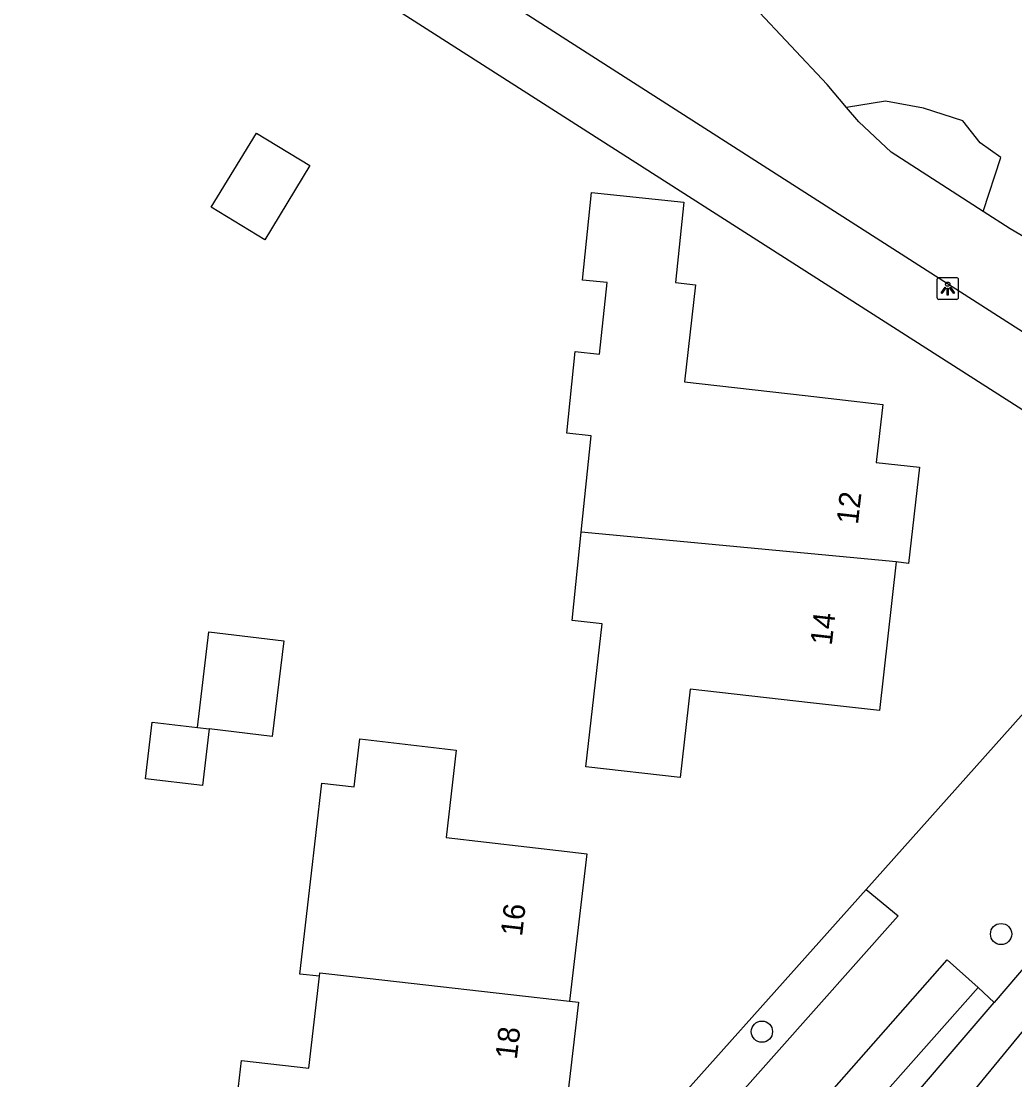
# Model space of a CAD drawing. Extents: x 162398 to 163643, y 386453 to 387397.
# Drawn here: x 162930.19 to 162976.02, y 386684.22 to 386733.04 of the extents above; entities that cross this region are included whole.
import ezdxf

# ---------------------------------------------------------------- set-up
doc = ezdxf.new("R2010")
doc.units = 0
for name, color, linetype in [('IMGEO_Boom', 7, 'Continuous'), ('IMGEO_Groenvoorziening', 7, 'Continuous'), ('IMGEO_Lichtpunt', 7, 'Continuous'), ('IMGEO_Pand', 7, 'Continuous'), ('IMGEO_Pand_nummerreeks', 7, 'Continuous'), ('IMGEO_Rijbaan_lokaal_gesloten', 7, 'Continuous'), ('IMGEO_Voetpad_open', 7, 'Continuous')]:
    doc.layers.add(name, color=color, linetype=linetype)

msp = doc.modelspace()

# ---------------------------------------------------------------- linework, layer by layer
at = {"layer": 'IMGEO_Boom'}
for centre in [(162975.387, 386690.945), (162964.357, 386686.446)]:
    msp.add_circle(centre, 0.489, dxfattribs=at)
at = {"layer": 'IMGEO_Groenvoorziening'}
for points in [[(162968.263, 386729.057), (162967.364, 386730.111), (162964.012, 386733.678)], [(162974.555, 386724.265), (162975.371, 386726.745), (162974.416, 386727.436), (162973.62, 386728.445), (162971.815, 386729.029), (162970.063, 386729.348), (162968.263, 386729.057)], [(162974.555, 386724.265), (162970.324, 386726.991), (162968.831, 386728.392), (162968.263, 386729.057)], [(162989.383, 386718.664), (162983.806, 386718.926), (162982.995, 386719.246), (162975.81, 386723.457), (162974.555, 386724.265)], [(162957.707, 386680.182), (162969.169, 386692.999)]]:
    msp.add_lwpolyline(points, dxfattribs=at)
at = {"layer": 'IMGEO_Lichtpunt'}
for p, q in [((162972.43, 386721.114), (162972.43, 386720.307)), ((162972.43, 386721.114), (162972.43, 386720.307)), ((162973.332, 386721.209), (162972.524, 386721.209)), ((162973.332, 386721.209), (162972.524, 386721.209)), ((162973.426, 386720.307), (162973.426, 386721.114)), ((162973.426, 386720.307), (162973.426, 386721.114)), ((162972.524, 386720.213), (162973.332, 386720.213)), ((162972.524, 386720.213), (162973.332, 386720.213))]:
    msp.add_line(p, q, dxfattribs=at)
for points in [[(162972.804, 386720.778), (162972.843, 386720.75), (162972.655, 386720.488), (162972.617, 386720.515), (162972.804, 386720.778)], [(162972.906, 386720.73), (162972.953, 386720.73), (162972.953, 386720.408), (162972.906, 386720.408), (162972.906, 386720.73)], [(162973.016, 386720.75), (162973.054, 386720.777), (162973.241, 386720.515), (162973.202, 386720.487), (162973.016, 386720.75)]]:
    msp.add_lwpolyline(points, dxfattribs=at)
msp.add_circle((162972.929, 386720.912), 0.0994, dxfattribs=at)
for centre, start, end in [((162972.524, 386721.114), 90, 180), ((162972.524, 386721.114), 90, 180), ((162973.332, 386721.114), 0, 90), ((162973.332, 386721.114), 0, 90), ((162972.524, 386720.307), 180, 270), ((162972.524, 386720.307), 180, 270), ((162973.332, 386720.307), 270, 0), ((162973.332, 386720.307), 270, 360)]:
    msp.add_arc(centre, 0.0946, start, end, dxfattribs=at)
at = {"layer": 'IMGEO_Pand'}
for points in [[(162938.962, 386724.457), (162941.047, 386727.882), (162943.508, 386726.384), (162941.423, 386722.959), (162938.962, 386724.457)], [(162956.024, 386709.48), (162956.483, 386713.921), (162955.357, 386714.037), (162955.747, 386717.808), (162956.872, 386717.691), (162957.212, 386720.986), (162956.086, 386721.102), (162956.503, 386725.141), (162960.758, 386724.7), (162960.374, 386720.991), (162961.298, 386720.886), (162960.789, 386716.404), (162966.35, 386715.773), (162969.927, 386715.367), (162969.624, 386712.693), (162971.622, 386712.466), (162971.12, 386708.039), (162970.552, 386708.103)], [(162970.552, 386708.103), (162969.775, 386701.249), (162966.596, 386701.61), (162961.048, 386702.239), (162960.586, 386698.168), (162956.239, 386698.661), (162956.986, 386705.244), (162955.602, 386705.401), (162956.024, 386709.48)], [(162970.552, 386708.103), (162956.024, 386709.48)], [(162938.32, 386700.477), (162938.85, 386704.888), (162942.305, 386704.472), (162941.774, 386700.054), (162938.857, 386700.411)], [(162938.857, 386700.411), (162938.553, 386697.793), (162935.929, 386698.098), (162936.233, 386700.719), (162938.32, 386700.477)], [(162938.32, 386700.477), (162938.857, 386700.411)], [(162943.946, 386689.002), (162943.045, 386689.101), (162943.538, 386693.351), (162944.066, 386697.904), (162945.549, 386697.732), (162945.806, 386699.946), (162950.259, 386699.43), (162949.792, 386695.4), (162955.382, 386694.753), (162956.276, 386694.649), (162955.488, 386687.856)], [(162955.488, 386687.856), (162955.897, 386687.809), (162955.378, 386683.332), (162953.512, 386683.549), (162953.2, 386680.862), (162949.972, 386681.236), (162944.341, 386681.888), (162943.87, 386677.818), (162939.566, 386678.317), (162940.354, 386685.115), (162943.453, 386684.755), (162943.946, 386689.002)], [(162943.946, 386689.002), (162943.964, 386689.161), (162945.467, 386688.986), (162955.488, 386687.856)]]:
    msp.add_lwpolyline(points, dxfattribs=at)
at = {"layer": 'IMGEO_Rijbaan_lokaal_gesloten'}
msp.add_lwpolyline([(162944.202, 386650.062), (162971.032, 386679.935), (162978.045, 386688.478), (162987.962, 386701.42), (162988.45, 386702.342)], dxfattribs=at)
at = {"layer": 'IMGEO_Voetpad_open'}
for points in [[(162986.397, 386712.298), (162986.082, 386712.5), (162952.63, 386733.915), (162927.211, 386750), (162923.157, 386752.565), (162923.129, 386752.583), (162922.957, 386752.706), (162922.868, 386752.783)], [(162984.352, 386710.007), (162921.76, 386750), (162921.361, 386750.255)], [(162969.169, 386692.999), (162984.352, 386710.007)], [(162969.169, 386692.999), (162970.648, 386691.781), (162959.175, 386678.871)], [(162963.515, 386679.089), (162972.906, 386689.751), (162974.326, 386688.48)], [(162976.679, 386689.682), (162975.063, 386687.793)], [(162974.326, 386688.48), (162964.913, 386677.848)], [(162975.063, 386687.793), (162974.326, 386688.48)], [(162965.843, 386677.132), (162969.738, 386681.565), (162975.063, 386687.793)]]:
    msp.add_lwpolyline(points, dxfattribs=at)

# ---------------------------------------------------------------- texts
at = {"layer": 'IMGEO_Pand_nummerreeks'}
for s, rotation, p in [('12', 83.5315, (162968.784, 386709.803)), ('14', 83.5315, (162967.577, 386704.23)), ('16', 83.3825, (162953.294, 386690.813)), ('18', 83.3883, (162953.05, 386685.133))]:
    msp.add_text(s, height=1, rotation=rotation, dxfattribs=at).set_placement(p)

doc.saveas('drawing.dxf')
